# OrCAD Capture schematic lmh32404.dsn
size A
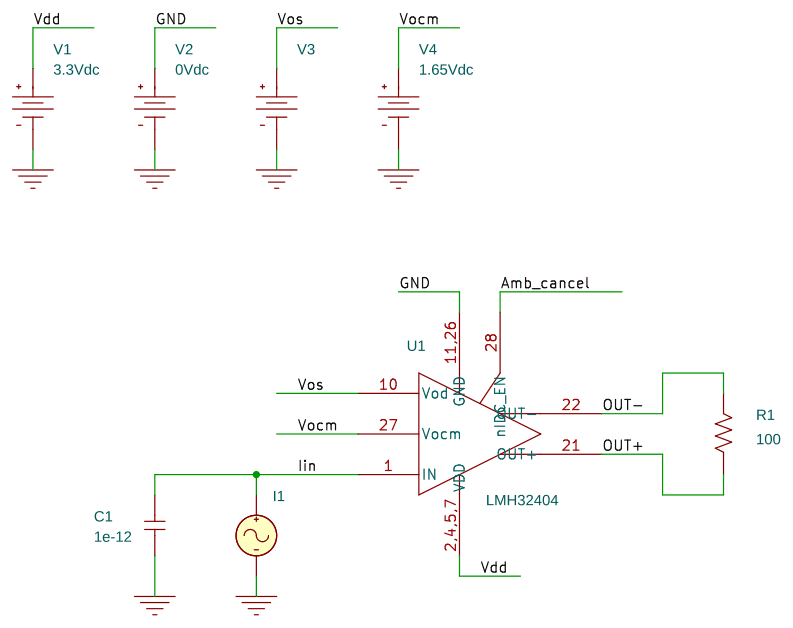
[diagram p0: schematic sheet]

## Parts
C1  1e-12  [cap196]
I1  IAC
R1  100  [AXRC05]
U1  LMH32404
V1  VDC
V2  VDC
V3  VDC
V4  VDC

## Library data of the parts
C1 = C
I1 = IAC
R1 = R
U1 = LMH32404
V1 = VDC: DC: 3.3Vdc
V2 = VDC: DC: 0Vdc
V3 = VDC
V4 = VDC: DC: 1.65Vdc

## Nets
GND: U1.11,26(GND) V2.0(+)
Vdd: U1.2,4,5,7(VDD) V1.0(+)
0: C1.2 I1.2(-) V1.1(-) V2.1(-) V3.1(-) V4.1(-)
Amb_cancel: U1.28(nIDC_EN)
Iin: C1.1 I1.1(+) U1.1(IN)
OUT+: R1.1 U1.21(OUT+)
OUT-: R1.2 U1.22(OUT-)
Vocm: U1.27(Vocm) V4.0(+)
Vos: U1.10(Vod) V3.0(+)
